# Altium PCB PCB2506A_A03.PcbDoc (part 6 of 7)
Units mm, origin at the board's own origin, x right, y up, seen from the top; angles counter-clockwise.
Board outline 115 x 60 mm, 6 copper layers (Top Layer, Signal Layer 2, Signal Layer 3, Signal Layer 4, Signal Layer 5, Bottom Layer), stack 1.555 mm thick; 376 components, 290 nets, 1297 pads, 901 vias.
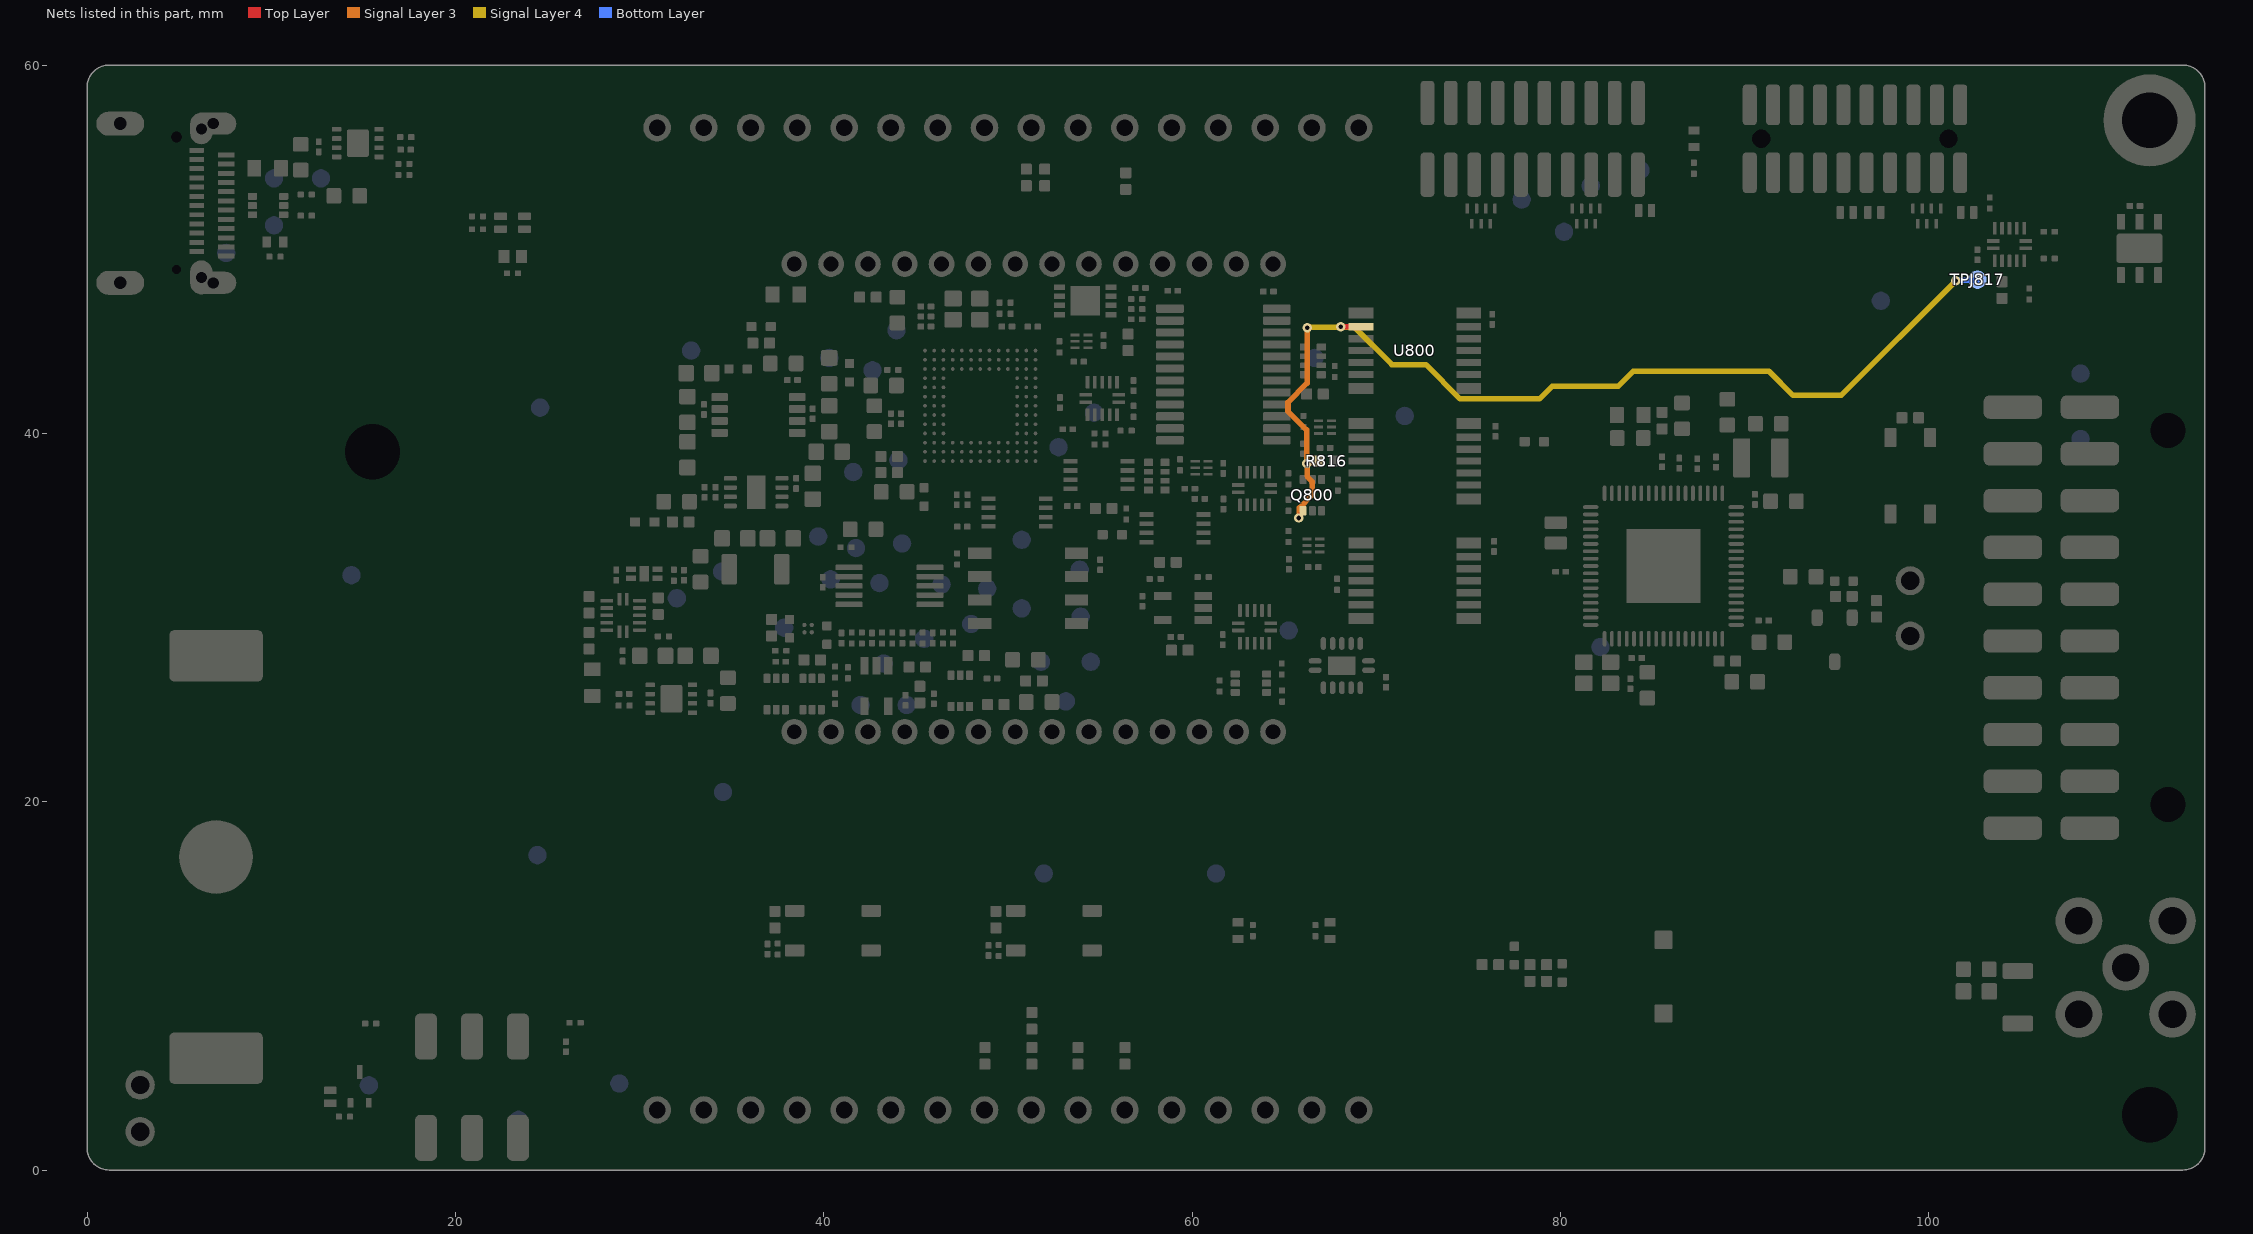
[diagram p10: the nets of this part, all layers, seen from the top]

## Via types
v1: diameter 0.508, hole 0.25, Top Layer to Bottom Layer, tented both sides, 901 vias

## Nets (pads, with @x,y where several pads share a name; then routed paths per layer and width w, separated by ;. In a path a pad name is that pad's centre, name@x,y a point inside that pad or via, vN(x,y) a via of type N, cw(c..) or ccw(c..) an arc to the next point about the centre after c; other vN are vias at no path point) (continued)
VTREF: Q800.4 R816.2 TPJ817.1 U800.2 | length 55.4
  Top Layer w0.3: v1(65.786,35.408) 65.826,35.447 65.826,35.53 66.033,35.738 Q800.4@66.033,35.8 ; v1(66.22,38.366) 66.26,38.406 66.807,38.406 R816.2@66.848,38.447 ; v1(68.083,45.801) 69.145,45.801 U800.2@69.148,45.798
  Signal Layer 3 w0.3: v1(65.786,35.408) 65.826,35.447 65.826,35.955 66.526,36.656 66.526,37.383 66.248,37.662 66.248,38.35 v1@66.218,38.379 ; v1(66.22,38.366) 66.218,38.368 66.218,40.192 65.211,41.199 65.211,41.691 66.252,42.731 v1(66.252,45.745)
  Signal Layer 4 w0.3: v1(66.252,45.745) 66.28,45.773 68.055,45.773 v1(68.083,45.801) ; v1@68.301,45.756 68.837,45.756 70.854,43.739 72.695,43.739 74.562,41.872 78.868,41.872 79.542,42.546 79.546,42.546 79.553,42.553 83.135,42.553 83.961,43.378 91.318,43.378 92.634,42.062 95.25,42.062 v1(101.473,48.285)
  Bottom Layer w0.3: v1(101.473,48.285) 101.505,48.318 102.618,48.318 TPJ817.1@102.65,48.35
pads on no net: D101.3 D800.5 D801.1 M2.1 M3.1 P101.M1 P101.M2 P601.25@1.8,56.82 P601.26@1.8,48.18 P601.27@6.2,56.525 P601.27@6.85,56.82 P601.28@6.2,48.475 P601.28@6.85,48.18 P601.A2 P601.A3 P601.A8 P601.A10 P601.A11 P601.B2 P601.B3 P601.B8 P601.B10 P601.B11 P601.M1 P601.M2 P800.7 P800.11 P800.13 P801.10 P801.12 P801.14 P801.16 P801.18 P801.20 P801.M1 P801.M2 RP800.2 RP800.7 U102.3 U102.4 U102.7 U600.8 U701.8 U808.8 U808.9 U808.10 U810.17 U900.B11 U900.E12 U900.F12 U900.G2 U900.H2 U900.J2 U900.L3 U900.L8 U900.L12 U900.M4 U900.M12 U900.N7 U900.N12 U901.9 U902.7

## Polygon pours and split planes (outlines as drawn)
VMCU on Signal Layer 5 "VMCU_L5" (solid, remove dead copper, pour order 5): 29.261,6.425 33.223,10.387 33.223,21.184 37.821,25.781 73.106,25.781 74.524,27.153 74.524,39.954 75.286,40.716 85.928,40.716 86.97,41.758 90.627,41.758 92.532,39.853 102.286,39.853 103.149,40.716 103.149,50.312 102.286,51.134 102.286,59.207 103.073,59.995 115,59.995 115,0 21.463,0 20.375,1.037 20.375,1.194 20.375,5.817 20.371,5.841 20.955,6.425
3V3 on Signal Layer 5 "3V3_L05_P014" (solid, remove dead copper, pour order 14): 18.587,44.526 27.259,44.526 29.439,42.291 41.595,42.291 43.798,40.056 45.314,40.056 46.673,38.697 46.673,35.878 44.975,34.18 39.463,34.18 38.049,32.766 38.049,30.226 36.601,28.778 33.223,28.778 28.804,24.359 25.908,24.359 16.84,33.426 14.732,33.426 14.199,32.893 14.199,30.099 17.875,26.423 17.875,8.425 19.391,6.909 29.009,6.909 32.614,10.514 32.614,21.464 37.515,26.365 73.076,26.365 73.939,27.229 73.939,39.954 75.235,41.25 85.649,41.25 86.69,42.291 90.653,42.291 92.569,40.375 102.249,40.375 102.692,40.818 102.692,50.114 102.006,50.8 102.006,59.284 101.815,59.475 99.825,59.475 99.4,59.05 99.4,53.782 95.993,50.375 77.682,50.375 70.656,57.299 68.451,57.301 63.372,52.222 21.32,52.222 19.238,54.305 13.513,54.305 12.802,53.594 12.802,50.388
5V on Signal Layer 5 "5V_L05_P013" (solid, remove dead copper, pour order 13): 29.108,41.783 26.822,44.069 18.491,44.069 18.161,44.348 12.319,50.19 12.319,53.975 13.208,54.864 19.877,54.864 21.782,52.925 63.212,52.925 67.945,57.658 71.018,57.658 77.851,50.825 95.85,50.825 99.035,54.01 99.035,58.979 98.563,59.45 7.913,59.45 7.65,59.187 7.65,36.927 8.377,36.2 12.903,36.2 14.554,34.595 16.637,34.595 26.264,24.968 28.6,24.968 32.791,29.159 36.398,29.159 37.541,30.302 37.541,32.766 39.446,34.671 44.577,34.671 46.228,36.322 46.228,38.1 44.768,39.56 43.624,39.56 41.402,41.783
GND on Signal Layer 5 "VCC Layer 5-GND" (solid, remove dead copper, pour order 15): 7.1,59.425 7.025,59.5 0.95,59.5 0.5,59.05 0.5,0.5 19.25,0.5 19.5,0.75 19.5,5.775 17.1,8.175 17.1,26.175 12.637,30.638 12.637,34.938 11.95,35.625 7.625,35.65 7.1,36.175
GND on Signal Layer 2 "GND_L2" (solid, remove dead copper, pour order 9): 0,0 0,60 125,60 125,0
GND on Top Layer "GND_L1" (solid, remove dead copper, pour order 2): 0,0 0,60 125,60 125,0
GND on Bottom Layer "GND_L6" (solid, remove dead copper, pour order 8): 0,0 0,60 125,60 125,0
GND on Signal Layer 3 "GND_L3" (solid, remove dead copper, pour order 11): 0,0 0,60 125,60 125,0
GND on Signal Layer 4 "GND_L4" (solid, remove dead copper, pour order 12): 0.008,-0.345 0.008,59.655 125.008,59.655 125.008,-0.345

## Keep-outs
Bottom Layer:
  region: 68.251,54.062 ccw(c69.051,54.062) 69.051,53.262 ccw(c69.051,54.062) 69.851,54.062 ccw(c69.051,54.062) 69.051,54.862 ccw(c69.051,54.062)
  region: 65.711,54.062 ccw(c66.511,54.062) 66.511,53.262 ccw(c66.511,54.062) 67.311,54.062 ccw(c66.511,54.062) 66.511,54.862 ccw(c66.511,54.062)
  region: 63.171,54.062 ccw(c63.971,54.062) 63.971,53.262 ccw(c63.971,54.062) 64.771,54.062 ccw(c63.971,54.062) 63.971,54.862 ccw(c63.971,54.062)
  region: 60.631,54.062 ccw(c61.431,54.062) 61.431,53.262 ccw(c61.431,54.062) 62.231,54.062 ccw(c61.431,54.062) 61.431,54.862 ccw(c61.431,54.062)
  region: 58.091,54.062 ccw(c58.891,54.062) 58.891,53.262 ccw(c58.891,54.062) 59.691,54.062 ccw(c58.891,54.062) 58.891,54.862 ccw(c58.891,54.062)
  region: 55.551,54.062 ccw(c56.351,54.062) 56.351,53.262 ccw(c56.351,54.062) 57.151,54.062 ccw(c56.351,54.062) 56.351,54.862 ccw(c56.351,54.062)
  region: 53.011,54.062 ccw(c53.811,54.062) 53.811,53.262 ccw(c53.811,54.062) 54.611,54.062 ccw(c53.811,54.062) 53.811,54.862 ccw(c53.811,54.062)
  region: 50.471,54.062 ccw(c51.271,54.062) 51.271,53.262 ccw(c51.271,54.062) 52.071,54.062 ccw(c51.271,54.062) 51.271,54.862 ccw(c51.271,54.062)
  region: 47.931,54.062 ccw(c48.731,54.062) 48.731,53.262 ccw(c48.731,54.062) 49.531,54.062 ccw(c48.731,54.062) 48.731,54.862 ccw(c48.731,54.062)
  region: 45.391,54.062 ccw(c46.191,54.062) 46.191,53.262 ccw(c46.191,54.062) 46.991,54.062 ccw(c46.191,54.062) 46.191,54.862 ccw(c46.191,54.062)
  region: 42.851,54.062 ccw(c43.651,54.062) 43.651,53.262 ccw(c43.651,54.062) 44.451,54.062 ccw(c43.651,54.062) 43.651,54.862 ccw(c43.651,54.062)
  region: 40.311,54.062 ccw(c41.111,54.062) 41.111,53.262 ccw(c41.111,54.062) 41.911,54.062 ccw(c41.111,54.062) 41.111,54.862 ccw(c41.111,54.062)
  region: 37.771,54.062 ccw(c38.571,54.062) 38.571,53.262 ccw(c38.571,54.062) 39.371,54.062 ccw(c38.571,54.062) 38.571,54.862 ccw(c38.571,54.062)
  region: 35.231,54.062 ccw(c36.031,54.062) 36.031,53.262 ccw(c36.031,54.062) 36.831,54.062 ccw(c36.031,54.062) 36.031,54.862 ccw(c36.031,54.062)
  region: 32.691,54.062 ccw(c33.491,54.062) 33.491,53.262 ccw(c33.491,54.062) 34.291,54.062 ccw(c33.491,54.062) 33.491,54.862 ccw(c33.491,54.062)
  region: 30.151,54.062 ccw(c30.951,54.062) 30.951,53.262 ccw(c30.951,54.062) 31.751,54.062 ccw(c30.951,54.062) 30.951,54.862 ccw(c30.951,54.062)
  region: 30.151,54.062 ccw(c30.951,54.062) 30.951,53.262 ccw(c30.951,54.062) 31.751,54.062 ccw(c30.951,54.062) 30.951,54.862 ccw(c30.951,54.062)
  region: 30.151,56.602 ccw(c30.951,56.602) 30.951,55.802 ccw(c30.951,56.602) 31.751,56.602 ccw(c30.951,56.602) 30.951,57.402 ccw(c30.951,56.602)
  region: 68.251,56.602 ccw(c69.051,56.602) 69.051,55.802 ccw(c69.051,56.602) 69.851,56.602 ccw(c69.051,56.602) 69.051,57.402 ccw(c69.051,56.602)
  region: 65.711,56.602 ccw(c66.511,56.602) 66.511,55.802 ccw(c66.511,56.602) 67.311,56.602 ccw(c66.511,56.602) 66.511,57.402 ccw(c66.511,56.602)
  region: 63.171,56.602 ccw(c63.971,56.602) 63.971,55.802 ccw(c63.971,56.602) 64.771,56.602 ccw(c63.971,56.602) 63.971,57.402 ccw(c63.971,56.602)
  region: 60.631,56.602 ccw(c61.431,56.602) 61.431,55.802 ccw(c61.431,56.602) 62.231,56.602 ccw(c61.431,56.602) 61.431,57.402 ccw(c61.431,56.602)
  region: 58.091,56.602 ccw(c58.891,56.602) 58.891,55.802 ccw(c58.891,56.602) 59.691,56.602 ccw(c58.891,56.602) 58.891,57.402 ccw(c58.891,56.602)
  region: 55.551,56.602 ccw(c56.351,56.602) 56.351,55.802 ccw(c56.351,56.602) 57.151,56.602 ccw(c56.351,56.602) 56.351,57.402 ccw(c56.351,56.602)
  region: 53.011,56.602 ccw(c53.811,56.602) 53.811,55.802 ccw(c53.811,56.602) 54.611,56.602 ccw(c53.811,56.602) 53.811,57.402 ccw(c53.811,56.602)
  region: 50.471,56.602 ccw(c51.271,56.602) 51.271,55.802 ccw(c51.271,56.602) 52.071,56.602 ccw(c51.271,56.602) 51.271,57.402 ccw(c51.271,56.602)
  region: 47.931,56.602 ccw(c48.731,56.602) 48.731,55.802 ccw(c48.731,56.602) 49.531,56.602 ccw(c48.731,56.602) 48.731,57.402 ccw(c48.731,56.602)
  region: 45.391,56.602 ccw(c46.191,56.602) 46.191,55.802 ccw(c46.191,56.602) 46.991,56.602 ccw(c46.191,56.602) 46.191,57.402 ccw(c46.191,56.602)
  region: 42.851,56.602 ccw(c43.651,56.602) 43.651,55.802 ccw(c43.651,56.602) 44.451,56.602 ccw(c43.651,56.602) 43.651,57.402 ccw(c43.651,56.602)
  region: 40.311,56.602 ccw(c41.111,56.602) 41.111,55.802 ccw(c41.111,56.602) 41.911,56.602 ccw(c41.111,56.602) 41.111,57.402 ccw(c41.111,56.602)
  region: 37.771,56.602 ccw(c38.571,56.602) 38.571,55.802 ccw(c38.571,56.602) 39.371,56.602 ccw(c38.571,56.602) 38.571,57.402 ccw(c38.571,56.602)
  region: 35.231,56.602 ccw(c36.031,56.602) 36.031,55.802 ccw(c36.031,56.602) 36.831,56.602 ccw(c36.031,56.602) 36.031,57.402 ccw(c36.031,56.602)
  region: 32.691,56.602 ccw(c33.491,56.602) 33.491,55.802 ccw(c33.491,56.602) 34.291,56.602 ccw(c33.491,56.602) 33.491,57.402 ccw(c33.491,56.602)
  region: 68.251,3.262 ccw(c69.051,3.262) 69.051,2.462 ccw(c69.051,3.262) 69.851,3.262 ccw(c69.051,3.262) 69.051,4.062 ccw(c69.051,3.262)
  region: 65.711,3.262 ccw(c66.511,3.262) 66.511,2.462 ccw(c66.511,3.262) 67.311,3.262 ccw(c66.511,3.262) 66.511,4.062 ccw(c66.511,3.262)
  region: 63.171,3.262 ccw(c63.971,3.262) 63.971,2.462 ccw(c63.971,3.262) 64.771,3.262 ccw(c63.971,3.262) 63.971,4.062 ccw(c63.971,3.262)
  region: 60.631,3.262 ccw(c61.431,3.262) 61.431,2.462 ccw(c61.431,3.262) 62.231,3.262 ccw(c61.431,3.262) 61.431,4.062 ccw(c61.431,3.262)
  region: 58.091,3.262 ccw(c58.891,3.262) 58.891,2.462 ccw(c58.891,3.262) 59.691,3.262 ccw(c58.891,3.262) 58.891,4.062 ccw(c58.891,3.262)
  region: 55.551,3.262 ccw(c56.351,3.262) 56.351,2.462 ccw(c56.351,3.262) 57.151,3.262 ccw(c56.351,3.262) 56.351,4.062 ccw(c56.351,3.262)
  region: 53.011,3.262 ccw(c53.811,3.262) 53.811,2.462 ccw(c53.811,3.262) 54.611,3.262 ccw(c53.811,3.262) 53.811,4.062 ccw(c53.811,3.262)
  region: 50.471,3.262 ccw(c51.271,3.262) 51.271,2.462 ccw(c51.271,3.262) 52.071,3.262 ccw(c51.271,3.262) 51.271,4.062 ccw(c51.271,3.262)
  region: 47.931,3.262 ccw(c48.731,3.262) 48.731,2.462 ccw(c48.731,3.262) 49.531,3.262 ccw(c48.731,3.262) 48.731,4.062 ccw(c48.731,3.262)
  region: 45.391,3.262 ccw(c46.191,3.262) 46.191,2.462 ccw(c46.191,3.262) 46.991,3.262 ccw(c46.191,3.262) 46.191,4.062 ccw(c46.191,3.262)
  region: 42.851,3.262 ccw(c43.651,3.262) 43.651,2.462 ccw(c43.651,3.262) 44.451,3.262 ccw(c43.651,3.262) 43.651,4.062 ccw(c43.651,3.262)
  region: 40.311,3.262 ccw(c41.111,3.262) 41.111,2.462 ccw(c41.111,3.262) 41.911,3.262 ccw(c41.111,3.262) 41.111,4.062 ccw(c41.111,3.262)
  region: 37.771,3.262 ccw(c38.571,3.262) 38.571,2.462 ccw(c38.571,3.262) 39.371,3.262 ccw(c38.571,3.262) 38.571,4.062 ccw(c38.571,3.262)
  region: 35.231,3.262 ccw(c36.031,3.262) 36.031,2.462 ccw(c36.031,3.262) 36.831,3.262 ccw(c36.031,3.262) 36.031,4.062 ccw(c36.031,3.262)
  region: 32.691,3.262 ccw(c33.491,3.262) 33.491,2.462 ccw(c33.491,3.262) 34.291,3.262 ccw(c33.491,3.262) 33.491,4.062 ccw(c33.491,3.262)
  region: 30.151,3.262 ccw(c30.951,3.262) 30.951,2.462 ccw(c30.951,3.262) 31.751,3.262 ccw(c30.951,3.262) 30.951,4.062 ccw(c30.951,3.262)
  region: 30.151,3.262 ccw(c30.951,3.262) 30.951,2.462 ccw(c30.951,3.262) 31.751,3.262 ccw(c30.951,3.262) 30.951,4.062 ccw(c30.951,3.262)
  region: 30.151,5.802 ccw(c30.951,5.802) 30.951,5.002 ccw(c30.951,5.802) 31.751,5.802 ccw(c30.951,5.802) 30.951,6.602 ccw(c30.951,5.802)
  region: 68.251,5.802 ccw(c69.051,5.802) 69.051,5.002 ccw(c69.051,5.802) 69.851,5.802 ccw(c69.051,5.802) 69.051,6.602 ccw(c69.051,5.802)
  region: 65.711,5.802 ccw(c66.511,5.802) 66.511,5.002 ccw(c66.511,5.802) 67.311,5.802 ccw(c66.511,5.802) 66.511,6.602 ccw(c66.511,5.802)
  region: 63.171,5.802 ccw(c63.971,5.802) 63.971,5.002 ccw(c63.971,5.802) 64.771,5.802 ccw(c63.971,5.802) 63.971,6.602 ccw(c63.971,5.802)
  region: 60.631,5.802 ccw(c61.431,5.802) 61.431,5.002 ccw(c61.431,5.802) 62.231,5.802 ccw(c61.431,5.802) 61.431,6.602 ccw(c61.431,5.802)
  region: 58.091,5.802 ccw(c58.891,5.802) 58.891,5.002 ccw(c58.891,5.802) 59.691,5.802 ccw(c58.891,5.802) 58.891,6.602 ccw(c58.891,5.802)
  region: 55.551,5.802 ccw(c56.351,5.802) 56.351,5.002 ccw(c56.351,5.802) 57.151,5.802 ccw(c56.351,5.802) 56.351,6.602 ccw(c56.351,5.802)
  region: 53.011,5.802 ccw(c53.811,5.802) 53.811,5.002 ccw(c53.811,5.802) 54.611,5.802 ccw(c53.811,5.802) 53.811,6.602 ccw(c53.811,5.802)
  region: 50.471,5.802 ccw(c51.271,5.802) 51.271,5.002 ccw(c51.271,5.802) 52.071,5.802 ccw(c51.271,5.802) 51.271,6.602 ccw(c51.271,5.802)
  region: 47.931,5.802 ccw(c48.731,5.802) 48.731,5.002 ccw(c48.731,5.802) 49.531,5.802 ccw(c48.731,5.802) 48.731,6.602 ccw(c48.731,5.802)
  region: 45.391,5.802 ccw(c46.191,5.802) 46.191,5.002 ccw(c46.191,5.802) 46.991,5.802 ccw(c46.191,5.802) 46.191,6.602 ccw(c46.191,5.802)
  region: 42.851,5.802 ccw(c43.651,5.802) 43.651,5.002 ccw(c43.651,5.802) 44.451,5.802 ccw(c43.651,5.802) 43.651,6.602 ccw(c43.651,5.802)
  region: 40.311,5.802 ccw(c41.111,5.802) 41.111,5.002 ccw(c41.111,5.802) 41.911,5.802 ccw(c41.111,5.802) 41.111,6.602 ccw(c41.111,5.802)
  region: 37.771,5.802 ccw(c38.571,5.802) 38.571,5.002 ccw(c38.571,5.802) 39.371,5.802 ccw(c38.571,5.802) 38.571,6.602 ccw(c38.571,5.802)
  region: 35.231,5.802 ccw(c36.031,5.802) 36.031,5.002 ccw(c36.031,5.802) 36.831,5.802 ccw(c36.031,5.802) 36.031,6.602 ccw(c36.031,5.802)
  region: 32.691,5.802 ccw(c33.491,5.802) 33.491,5.002 ccw(c33.491,5.802) 34.291,5.802 ccw(c33.491,5.802) 33.491,6.602 ccw(c33.491,5.802)
  region: 103.5,19 cw(c103.5,18.5) 104,18.5 cw(c103.5,18.5) 103.5,18 cw(c103.5,18.5) 103,18.5 cw(c103.5,18.5)
  region: 108.25,40.2 cw(c108.25,39.699) 108.75,39.7 cw(c108.25,39.7) 108.25,39.2 cw(c108.25,39.7) 107.75,39.7 cw(c108.25,39.699)
  region: 108.25,43.748 cw(c108.25,43.248) 108.75,43.248 cw(c108.25,43.248) 108.25,42.748 cw(c108.25,43.248) 107.75,43.248 cw(c108.25,43.248)
  region: 107,54.2 cw(c107,53.7) 107.5,53.7 cw(c107,53.7) 107,53.2 cw(c107,53.7) 106.5,53.7 cw(c107,53.7)
  region: 105.4,52.498 cw(c105.4,51.998) 105.9,51.998 cw(c105.4,51.998) 105.4,51.498 cw(c105.4,51.998) 104.9,51.998 cw(c105.4,51.998)
  region: 104.45,54.2 cw(c104.45,53.7) 104.95,53.7 cw(c104.45,53.7) 104.45,53.2 cw(c104.45,53.7) 103.95,53.7 cw(c104.45,53.7)
  region: 103.399,52.498 cw(c103.399,51.998) 103.899,51.998 cw(c103.399,51.998) 103.399,51.498 cw(c103.399,51.998) 102.899,51.998 cw(c103.399,51.998)
  region: 102.649,48.848 cw(c102.649,48.348) 103.149,48.348 cw(c102.649,48.348) 102.649,47.848 cw(c102.649,48.348) 102.149,48.348 cw(c102.649,48.348)
  region: 97.399,47.7 cw(c97.399,47.2) 97.899,47.2 cw(c97.399,47.2) 97.399,46.7 cw(c97.399,47.2) 96.899,47.2 cw(c97.399,47.2)
  region: 92.525,52.432 cw(c92.525,51.932) 93.025,51.932 cw(c92.525,51.932) 92.525,51.432 cw(c92.525,51.932) 92.025,51.932 cw(c92.525,51.932)
  region: 93.541,54.21 cw(c93.541,53.71) 94.041,53.71 cw(c93.541,53.71) 93.541,53.21 cw(c93.541,53.71) 93.041,53.71 cw(c93.541,53.71)
  region: 90.493,52.432 cw(c90.493,51.932) 90.993,51.932 cw(c90.493,51.932) 90.493,51.432 cw(c90.493,51.932) 89.993,51.932 cw(c90.493,51.932)
  region: 88.461,52.432 cw(c88.461,51.932) 88.961,51.932 cw(c88.461,51.932) 88.461,51.432 cw(c88.461,51.932) 87.961,51.932 cw(c88.461,51.932)
  region: 89.477,54.21 cw(c89.477,53.71) 89.977,53.71 cw(c89.477,53.71) 89.477,53.21 cw(c89.477,53.71) 88.977,53.71 cw(c89.477,53.71)
  region: 87.466,54.206 cw(c87.467,53.706) 87.967,53.706 cw(c87.466,53.707) 87.466,53.206 cw(c87.466,53.706) 86.967,53.706 cw(c87.467,53.706)
  region: 84.349,54.799 cw(c84.349,54.299) 84.849,54.3 cw(c84.349,54.3) 84.349,53.799 cw(c84.349,54.299) 83.849,54.299 cw(c84.349,54.299)
  region: 85.4,52.198 cw(c85.4,51.698) 85.9,51.699 cw(c85.4,51.699) 85.4,51.199 cw(c85.4,51.698) 84.9,51.698 cw(c85.4,51.698)
  region: 93.449,42.798 cw(c93.45,42.298) 93.95,42.298 cw(c93.449,42.298) 93.449,41.798 cw(c93.449,42.298) 92.949,42.298 cw(c93.45,42.298)
  region: 86.15,40.05 cw(c86.15,39.55) 86.65,39.55 cw(c86.149,39.55) 86.149,39.05 cw(c86.149,39.55) 85.65,39.55 cw(c86.15,39.55)
  region: 81.649,53.949 cw(c81.649,53.449) 82.149,53.449 cw(c81.649,53.449) 81.649,52.949 cw(c81.649,53.449) 81.149,53.449 cw(c81.649,53.448)
  region: 77.9,53.199 cw(c77.9,52.699) 78.4,52.699 cw(c77.9,52.699) 77.9,52.199 cw(c77.9,52.699) 77.4,52.699 cw(c77.9,52.699)
  region: 80.201,51.449 cw(c80.201,50.949) 80.701,50.949 cw(c80.201,50.949) 80.201,50.449 cw(c80.201,50.949) 79.701,50.949 cw(c80.201,50.949)
  region: 77.399,48.498 cw(c77.399,47.998) 77.899,47.998 cw(c77.399,47.998) 77.399,47.498 cw(c77.399,47.998) 76.899,47.998 cw(c77.399,47.998)
  region: 75.4,48.498 cw(c75.4,47.998) 75.9,47.998 cw(c75.4,47.998) 75.4,47.498 cw(c75.4,47.998) 74.9,47.998 cw(c75.4,47.998)
  region: 73.399,48.498 cw(c73.399,47.998) 73.899,47.998 cw(c73.399,47.998) 73.399,47.498 cw(c73.399,47.998) 72.899,47.998 cw(c73.399,47.998)
  region: 77.399,46.298 cw(c77.399,45.798) 77.899,45.798 cw(c77.399,45.798) 77.399,45.298 cw(c77.399,45.798) 76.899,45.798 cw(c77.399,45.798)
  region: 75.4,46.298 cw(c75.4,45.798) 75.9,45.798 cw(c75.4,45.798) 75.4,45.298 cw(c75.4,45.798) 74.9,45.798 cw(c75.4,45.798)
  region: 73.399,46.298 cw(c73.399,45.798) 73.899,45.798 cw(c73.399,45.798) 73.399,45.298 cw(c73.399,45.798) 72.899,45.798 cw(c73.399,45.798)
  region: 71.4,46.298 cw(c71.4,45.798) 71.9,45.798 cw(c71.4,45.798) 71.4,45.298 cw(c71.4,45.798) 70.9,45.798 cw(c71.4,45.798)
  region: 73.399,43.598 cw(c73.399,43.098) 73.899,43.098 cw(c73.399,43.098) 73.399,42.598 cw(c73.399,43.098) 72.899,43.098 cw(c73.399,43.098)
  region: 71.55,41.449 cw(c71.55,40.949) 72.05,40.949 cw(c71.55,40.949) 71.55,40.449 cw(c71.55,40.949) 71.05,40.949 cw(c71.55,40.949)
  region: 66.65,44.599 cw(c66.65,44.099) 67.15,44.099 cw(c66.65,44.099) 66.65,43.599 cw(c66.65,44.099) 66.15,44.099 cw(c66.65,44.099)
  region: 94.199,12.348 cw(c94.199,11.848) 94.699,11.848 cw(c94.199,11.849) 94.199,11.348 cw(c94.199,11.848) 93.699,11.848 cw(c94.199,11.848)
  region: 96.8,11.8 cw(c96.8,11.3) 97.3,11.3 cw(c96.8,11.3) 96.8,10.8 cw(c96.8,11.3) 96.3,11.3 cw(c96.8,11.3)
  region: 93.249,9.948 cw(c93.249,9.448) 93.749,9.448 cw(c93.249,9.448) 93.249,8.948 cw(c93.249,9.448) 92.749,9.448 cw(c93.249,9.448)
  region: 96.5,9.148 cw(c96.5,8.648) 97,8.648 cw(c96.5,8.648) 96.5,8.148 cw(c96.5,8.648) 96,8.648 cw(c96.5,8.648)
  region: 95.7,6.55 cw(c95.7,6.05) 96.2,6.05 cw(c95.7,6.05) 95.7,5.55 cw(c95.7,6.05) 95.2,6.05 cw(c95.7,6.049)
  region: 93.249,7.398 cw(c93.249,6.898) 93.749,6.898 cw(c93.249,6.898) 93.249,6.398 cw(c93.249,6.898) 92.749,6.898 cw(c93.249,6.898)
  region: 81.499,10.949 cw(c81.499,10.449) 81.999,10.449 cw(c81.499,10.449) 81.499,9.949 cw(c81.499,10.449) 80.999,10.449 cw(c81.499,10.449)
  region: 77.249,10.949 cw(c77.249,10.449) 77.749,10.449 cw(c77.249,10.449) 77.249,9.949 cw(c77.249,10.449) 76.749,10.449 cw(c77.249,10.449)
  region: 72.949,10.949 cw(c72.949,10.449) 73.449,10.449 cw(c72.949,10.449) 72.949,9.949 cw(c72.949,10.449) 72.449,10.449 cw(c72.949,10.449)
  region: 74.1,6.748 cw(c74.1,6.248) 74.6,6.248 cw(c74.1,6.248) 74.1,5.748 cw(c74.1,6.248) 73.6,6.248 cw(c74.1,6.248)
  region: 54.674,41.624 cw(c54.674,41.124) 55.174,41.125 cw(c54.674,41.125) 54.674,40.625 cw(c54.674,41.124) 54.174,41.124 cw(c54.674,41.124)
  region: 52.749,39.75 cw(c52.749,39.25) 53.249,39.25 cw(c52.748,39.25) 52.748,38.75 cw(c52.748,39.25) 52.249,39.25 cw(c52.749,39.25)
  region: 50.75,34.723 cw(c50.75,34.223) 51.25,34.223 cw(c50.749,34.223) 50.75,33.723 cw(c50.75,34.223) 50.25,34.223 cw(c50.75,34.223)
  region: 53.899,33.098 cw(c53.899,32.598) 54.399,32.598 cw(c53.899,32.598) 53.899,32.098 cw(c53.899,32.598) 53.399,32.598 cw(c53.899,32.598)
  region: 50.75,31 cw(c50.75,30.5) 51.25,30.5 cw(c50.749,30.5) 50.75,30 cw(c50.75,30.5) 50.25,30.5 cw(c50.75,30.5)
  region: 53.95,30.55 cw(c53.95,30.05) 54.45,30.05 cw(c53.95,30.05) 53.95,29.55 cw(c53.95,30.05) 53.45,30.05 cw(c53.95,30.05)
  region: 54.499,28.099 cw(c54.499,27.599) 54.999,27.599 cw(c54.498,27.599) 54.499,27.099 cw(c54.499,27.599) 53.999,27.599 cw(c54.499,27.599)
  region: 51.799,28.099 cw(c51.799,27.599) 52.299,27.599 cw(c51.798,27.599) 51.799,27.099 cw(c51.799,27.599) 51.299,27.599 cw(c51.799,27.599)
  region: 53.15,25.95 cw(c53.15,25.45) 53.65,25.45 cw(c53.15,25.45) 53.15,24.95 cw(c53.15,25.45) 52.65,25.45 cw(c53.15,25.45)
  region: 47.999,30.149 cw(c47.999,29.649) 48.499,29.649 cw(c47.999,29.649) 47.999,29.149 cw(c47.999,29.649) 47.499,29.649 cw(c47.999,29.649)
  region: 45.449,29.349 cw(c45.449,28.849) 45.949,28.849 cw(c45.448,28.849) 45.449,28.349 cw(c45.449,28.849) 44.949,28.849 cw(c45.449,28.849)
  region: 47,25.749 cw(c47.001,25.249) 47.501,25.25 cw(c47,25.25) 47,24.75 cw(c47,25.249) 46.501,25.249 cw(c47.001,25.249)
  region: 43.249,28 cw(c43.249,27.5) 43.749,27.5 cw(c43.249,27.5) 43.249,27 cw(c43.249,27.5) 42.749,27.5 cw(c43.249,27.5)
  region: 44.499,25.749 cw(c44.499,25.249) 44.999,25.25 cw(c44.499,25.25) 44.499,24.75 cw(c44.499,25.249) 43.999,25.249 cw(c44.499,25.249)
  region: 41.999,25.749 cw(c41.999,25.249) 42.499,25.25 cw(c41.999,25.25) 41.999,24.75 cw(c41.999,25.249) 41.499,25.249 cw(c41.999,25.249)
  region: 61.301,16.598 cw(c61.301,16.098) 61.801,16.098 cw(c61.301,16.098) 61.301,15.598 cw(c61.301,16.098) 60.801,16.098 cw(c61.301,16.098)
  region: 51.951,16.598 cw(c51.951,16.098) 52.451,16.098 cw(c51.951,16.098) 51.951,15.598 cw(c51.951,16.098) 51.451,16.098 cw(c51.951,16.098)
  region: 34.524,21.025 cw(c34.524,20.525) 35.024,20.525 cw(c34.524,20.525) 34.524,20.025 cw(c34.524,20.525) 34.024,20.525 cw(c34.524,20.525)
  region: 24.45,17.599 cw(c24.45,17.099) 24.95,17.099 cw(c24.45,17.099) 24.45,16.599 cw(c24.45,17.099) 23.95,17.099 cw(c24.45,17.098)
  region: 15.649,26.448 cw(c15.649,25.948) 16.149,25.948 cw(c15.649,25.948) 15.649,25.448 cw(c15.649,25.948) 15.149,25.948 cw(c15.649,25.948)
  region: 12.05,26.448 cw(c12.05,25.948) 12.55,25.948 cw(c12.05,25.948) 12.05,25.448 cw(c12.05,25.948) 11.55,25.948 cw(c12.05,25.948)
  region: 12.025,29.773 cw(c12.025,29.273) 12.525,29.273 cw(c12.025,29.273) 12.025,28.773 cw(c12.025,29.273) 11.525,29.273 cw(c12.025,29.273)
  region: 9.475,29.798 cw(c9.475,29.298) 9.975,29.298 cw(c9.474,29.298) 9.475,28.798 cw(c9.475,29.298) 8.975,29.298 cw(c9.475,29.298)
  region: 14.349,32.798 cw(c14.349,32.298) 14.849,32.298 cw(c14.349,32.298) 14.349,31.798 cw(c14.349,32.298) 13.849,32.298 cw(c14.349,32.298)
  region: 10.399,32.249 cw(c10.399,31.749) 10.899,31.749 cw(c10.399,31.75) 10.399,31.249 cw(c10.399,31.749) 9.899,31.749 cw(c10.399,31.749)
  region: 10.399,34.899 cw(c10.399,34.399) 10.899,34.399 cw(c10.399,34.399) 10.399,33.899 cw(c10.399,34.399) 9.899,34.399 cw(c10.399,34.398)
  region: 18.446,49.044 cw(c18.446,48.544) 18.946,48.544 cw(c18.446,48.544) 18.446,48.044 cw(c18.446,48.544) 17.946,48.544 cw(c18.446,48.544)
  region: 15.906,50.314 cw(c15.906,49.814) 16.406,49.814 cw(c15.906,49.814) 15.906,49.314 cw(c15.906,49.814) 15.406,49.814 cw(c15.906,49.814)
  region: 18.446,51.584 cw(c18.446,51.084) 18.946,51.084 cw(c18.446,51.084) 18.446,50.584 cw(c18.446,51.084) 17.946,51.084 cw(c18.446,51.084)
  region: 15.906,52.854 cw(c15.906,52.354) 16.406,52.354 cw(c15.906,52.354) 15.906,51.854 cw(c15.906,52.354) 15.406,52.354 cw(c15.906,52.354)
  region: 18.446,54.124 cw(c18.446,53.624) 18.946,53.624 cw(c18.446,53.624) 18.446,53.124 cw(c18.446,53.624) 17.946,53.624 cw(c18.446,53.624)
  region: 15.906,55.394 cw(c15.906,54.894) 16.406,54.894 cw(c15.906,54.894) 15.906,54.394 cw(c15.906,54.894) 15.406,54.894 cw(c15.906,54.894)
  region: 12.7,54.35 cw(c12.7,53.85) 13.2,53.85 cw(c12.7,53.85) 12.7,53.35 cw(c12.7,53.85) 12.2,53.85 cw(c12.7,53.85)
  region: 10.15,54.35 cw(c10.15,53.85) 10.65,53.85 cw(c10.15,53.85) 10.15,53.35 cw(c10.15,53.85) 9.65,53.85 cw(c10.15,53.85)
  region: 10.15,51.8 cw(c10.15,51.3) 10.65,51.3 cw(c10.15,51.3) 10.15,50.8 cw(c10.15,51.3) 9.65,51.3 cw(c10.15,51.3)
  region: 7.549,50.299 cw(c7.549,49.799) 8.049,49.799 cw(c7.549,49.799) 7.549,49.299 cw(c7.549,49.799) 7.049,49.799 cw(c7.549,49.798)
  region: 24.6,41.899 cw(c24.6,41.399) 25.1,41.399 cw(c24.6,41.399) 24.6,40.899 cw(c24.6,41.399) 24.1,41.399 cw(c24.6,41.399)
  region: 36.249,37.548 cw(c36.249,37.048) 36.749,37.048 cw(c36.249,37.048) 36.249,36.548 cw(c36.249,37.048) 35.749,37.048 cw(c36.249,37.048)
  region: 38.999,37.548 cw(c39,37.048) 39.5,37.048 cw(c38.999,37.048) 38.999,36.548 cw(c38.999,37.048) 38.5,37.048 cw(c39,37.048)
  region: 41.6,38.399 cw(c41.6,37.899) 42.101,37.899 cw(c41.6,37.899) 41.6,37.399 cw(c41.6,37.899) 41.1,37.899 cw(c41.601,37.899)
  region: 44.049,39.049 cw(c44.049,38.549) 44.549,38.549 cw(c44.049,38.549) 44.049,38.049 cw(c44.049,38.549) 43.549,38.549 cw(c44.049,38.549)
  region: 42.649,43.923 cw(c42.65,43.423) 43.15,43.423 cw(c42.649,43.423) 42.649,42.923 cw(c42.649,43.423) 42.149,43.423 cw(c42.65,43.423)
  region: 43.95,46.1 cw(c43.95,45.6) 44.45,45.6 cw(c43.95,45.6) 43.95,45.1 cw(c43.95,45.6) 43.45,45.6 cw(c43.95,45.6)
  region: 18.446,46.504 cw(c18.446,46.004) 18.946,46.004 cw(c18.446,46.004) 18.446,45.504 cw(c18.446,46.004) 17.946,46.004 cw(c18.446,46.004)

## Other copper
Top Layer:
  region net AEM_VMCU: 22.642,4.608 22.642,2.998 22.845,2.794 24.039,2.794 24.242,2.998 24.242,4.649 23.963,4.928 22.962,4.928
  region net VMCU: 20.142,4.597 20.142,3.023 20.345,2.819 21.539,2.819 21.742,3.023 21.742,4.674 21.463,4.953 20.498,4.953
  region net VMCU: 99.746,16.713 99.771,16.739 102.641,16.739 103.073,17.17 103.073,19.126 102.718,19.482 99.695,19.482 99.466,19.253 99.466,17.018 99.746,16.739
  pour cut-out: 89.518,25.958 89.746,25.958 90.146,25.958 90.146,29.616 89.518,29.616
  pour cut-out: 77.378,51.857 77.378,52.085 77.378,52.485 75.829,52.485 75.829,51.857
  pour cut-out: 71.542,52.822 71.77,52.822 72.17,52.822 72.17,54.372 71.542,54.372
  pour cut-out: 69.414,33.979 69.643,33.979 70.043,33.979 70.043,35.528 69.414,35.528
  pour cut-out: 37.582,48.753 37.582,48.524 37.582,48.124 39.132,48.124 39.132,48.753
  pour cut-out: 52.695,49.921 52.695,49.692 52.695,49.293 54.245,49.293 54.245,49.921
  pour cut-out: 44.104,45.958 43.876,45.958 43.476,45.958 43.476,44.409 44.104,44.409
  pour cut-out: 57.813,6.746 57.813,6.975 57.813,7.374 56.263,7.374 56.263,6.746
  pour cut-out: 58.064,53.518 57.276,56.354 55.88,55.702 55.88,53.594
  pour cut-out: 50.178,6.331 50.178,6.56 50.178,6.96 48.628,6.96 48.628,6.331
  region net N17065843: 89.937,36.075 89.937,35.894 90.018,35.814 90.907,35.814 91.034,35.814 91.11,35.89 91.11,36.144 90.983,36.271 89.992,36.271 89.916,36.195 89.937,36.174
  pour cut-out: 80.531,41.134 80.531,40.727 80.531,40.328 82.081,40.328 82.081,41.134
  pour cut-out: 75.881,42.328 75.474,42.328 75.075,42.328 75.075,40.779 75.881,40.779
  pour cut-out: 92.693,32.385 92.921,32.385 93.321,32.385 93.321,35.23 92.693,35.23
  pour cut-out: 93.929,30.066 93.929,29.837 93.929,29.437 95.606,29.437 95.606,30.066
  pour cut-out: 90.805,31.158 90.805,30.929 90.805,30.53 94.463,30.53 94.463,31.158
  pour cut-out: 71.564,36.62 71.564,36.391 71.564,35.992 74.232,35.992 74.232,36.62
  pour cut-out: 79.527,28.219 79.948,31.919 80.014,32.498 78.364,30.043
  pour cut-out: 78.943,32.983 79.571,32.983 79.571,35.763 78.943,35.763
  pour cut-out: 75.666,36.543 75.666,36.314 75.666,35.914 79.324,35.914 79.324,36.543
  pour cut-out: 59.919,28.27 61.417,28.27 61.417,29.489 59.919,29.489
  pour cut-out: 64.37,35.676 64.599,35.676 64.998,35.676 64.998,37.225 64.37,37.225
  pour cut-out: 106.077,47.715 106.305,47.715 106.705,47.715 106.705,49.265 106.077,49.265
  pour cut-out: 91.313,39.218 90.907,39.218 90.507,39.218 90.507,37.668 91.313,37.668
  pour cut-out: 97.995,31.978 96.67,31.978 96.27,31.978 96.27,31.369 97.995,31.369
  pour cut-out: 81.356,28.473 80.728,28.473 80.728,27.94 81.356,27.94
  pour cut-out: 37.827,12.509 38.056,12.509 38.456,12.509 38.456,14.059 37.827,14.059
  pour cut-out: 50.07,12.23 50.299,12.23 50.698,12.23 50.698,13.779 50.07,13.779
  pour cut-out: 5.813,50.745 5.813,50.516 5.813,50.117 7.362,50.117 7.362,50.745
  pour cut-out: 9.978,51.972 9.749,51.972 9.35,51.972 9.35,50.423 9.978,50.423
  pour cut-out: 10.211,54.31 10.211,54.938 6.074,54.938 6.074,54.31
  pour cut-out: 82.245,36.068 82.321,35.992 82.321,29.489 88.875,29.489 88.976,29.591 88.976,36.17 82.296,36.17 82.245,36.22
  pour cut-out: 45.222,48.047 45.222,48.275 45.222,48.675 43.672,48.675 43.672,48.047
  pour cut-out: 46.133,49.232 46.133,49.46 46.133,49.86 44.583,49.86 44.583,49.232
  pour cut-out: 56.133,49.232 56.133,49.46 56.133,49.86 54.583,49.86 54.583,49.232
  pour cut-out: 40.005,43.739 40.005,43.967 40.005,44.367 38.456,44.367 38.456,43.739
  pour cut-out: 34.366,41.834 34.595,41.834 34.994,41.834 34.994,43.383 34.366,43.383
  pour cut-out: 38.43,33.706 38.43,33.477 38.43,33.078 40.437,33.078 40.437,33.706
  pour cut-out: 51.729,31.858 51.729,31.63 51.729,31.23 54.534,31.23 54.534,31.858
  pour cut-out: 56.276,35.948 56.276,35.719 56.276,35.32 57.825,35.32 57.825,35.948
  pour cut-out: 60.391,41.206 60.391,40.977 60.391,40.577 61.94,40.577 61.94,41.206
  pour cut-out: 70.968,40.615 70.739,40.615 70.339,40.615 70.339,39.065 70.968,39.065
  pour cut-out: 74.279,39.608 73.558,41.478 73.558,41.878 72.009,41.878 72.009,41.25
  pour cut-out: 83.04,41.557 83.04,41.328 83.04,40.928 84.59,40.928 84.59,41.557
  pour cut-out: 71.476,51.45 71.476,51.221 71.476,50.93 73.026,50.394 73.026,51.45
  pour cut-out: 93.233,58.924 93.233,59.153 93.233,59.552 89.687,59.552 89.687,58.924
  pour cut-out: 94.92,52.304 95.148,52.304 95.548,52.304 95.548,53.854 94.92,53.854
  pour cut-out: 107.119,36.887 107.348,36.887 107.747,36.887 107.747,38.436 107.119,38.436
  pour cut-out: 109.659,36.912 109.888,36.912 110.287,36.912 110.287,38.461 109.659,38.461
  pour cut-out: 109.684,39.3 109.913,39.3 110.313,39.3 110.313,40.849 109.684,40.849
  pour cut-out: 107.119,39.274 107.348,39.274 107.747,39.274 107.747,40.824 107.119,40.824
  pour cut-out: 105.613,39.421 105.842,39.421 106.241,39.421 106.241,40.97 105.613,40.97
  pour cut-out: 89.027,29.287 89.027,28.038 92.055,28.038 92.055,29.287
  pour cut-out: 79.807,35.331 79.578,35.331 79.179,35.331 79.179,33.782 79.807,33.782
  pour cut-out: 71.003,30.499 71.003,30.727 71.003,31.127 69.454,31.127 69.454,30.499
  pour cut-out: 65.913,25.578 66.313,25.578 66.313,26.264 65.392,26.098
  pour cut-out: 50.622,23.774 50.622,23.546 50.622,23.146 52.172,23.146 52.172,23.774
  pour cut-out: 48.616,23.87 48.616,23.641 48.616,23.242 50.166,23.242 50.166,23.87
  pour cut-out: 42.57,23.87 42.57,23.242 48.057,23.242 48.057,23.87
  pour cut-out: 38.76,23.8 38.76,23.571 38.76,23.172 40.31,23.172 40.31,23.8
  pour cut-out: 81,15 90,15 90,6 81,6
  region net N16809528: 10.542,26.275 10.542,29.5 3.462,29.5 3.462,26.275
  region net N16809528: 3.458,7.725 3.458,5.542 4.5,4.5 10.538,4.5 10.538,7.725
Signal Layer 3:
  pour cut-out: 88.569,27.02 88.569,25.903 88.112,25.903 88.112,27.02
  pour cut-out: 91.268,48.674 92.386,48.674 92.386,48.216 91.268,48.216
  pour cut-out: 75.283,46.435 76.4,46.435 76.4,45.978 75.283,45.978
  pour cut-out: 91.883,45.399 90.144,43.659 89.586,44.526 91.516,45.999
  pour cut-out: 107.29,42.901 107.29,40.208 106.832,40.208 106.832,42.901
  pour cut-out: 76.124,51.841 76.124,50.724 75.667,50.724 75.667,51.841
  pour cut-out: 72.238,54.788 72.238,53.67 71.78,53.67 71.78,54.788
  pour cut-out: 46.05,44.323 44.933,44.323 44.933,44.78 46.05,44.78
  pour cut-out: 50.004,41.854 51.121,41.854 51.121,41.396 50.004,41.396
  pour cut-out: 53.188,43.866 54.305,43.866 54.305,43.409 53.188,43.409
  pour cut-out: 9.013,53.256 10.131,53.256 10.131,52.799 9.013,52.799
  pour cut-out: 60.985,30.124 60.985,29.007 60.528,29.007 60.528,30.124
  pour cut-out: 58.649,25.756 58.649,24.638 58.191,24.638 58.191,25.756
  pour cut-out: 54.686,34.519 54.686,33.401 54.229,33.401 54.229,34.519
  pour cut-out: 56.744,34.112 56.744,32.995 56.286,32.995 56.286,34.112
  pour cut-out: 58.275,35.636 57.157,35.636 57.157,36.093 58.275,36.093
  pour cut-out: 57.252,40.564 57.252,39.446 56.794,39.446 56.794,40.564
  pour cut-out: 87.02,25.705 85.903,25.705 85.903,26.162 87.02,26.162
  pour cut-out: 81.788,39.395 81.788,37.719 81.331,37.719 81.331,39.395
  pour cut-out: 39.205,25.46 39.205,24.342 37.109,24.342 37.109,25.46
  pour cut-out: 67.929,46.825 66.811,46.825 66.811,47.282 67.929,47.282
  pour cut-out: 62.253,28.041 61.135,28.041 61.135,28.498 62.253,28.498
  pour cut-out: 71.857,19.355 71.857,18.44 69.85,18.44 69.85,19.355
  pour cut-out: 109.957,46.241 109.957,44.691 109.499,44.691 109.499,46.241
  pour cut-out: 108.102,54.305 108.102,53.188 105.74,53.188 105.74,54.305
  pour cut-out: 12.7,51.308 11.582,51.308 11.582,51.765 12.7,51.765
  pour cut-out: 89.393,30.339 90.127,30.673 91.616,30.339 87.629,26.042
  pour cut-out: 102.184,39.04 102.184,37.922 101.727,37.922 101.727,39.04
  pour cut-out: 97.141,43.341 95.401,41.601 94.844,42.469 96.774,43.942
  pour cut-out: 89.477,47.82 89.23,48.438 89.002,48.768 90.239,49.699
  pour cut-out: 78.257,36.093 78.257,34.976 77.8,34.976 77.8,36.093
  pour cut-out: 79.324,29.769 78.207,29.769 78.207,30.226 79.324,30.226
  pour cut-out: 76.175,31.928 73.939,31.928 73.939,32.385 76.175,32.385
  pour cut-out: 74.778,45.491 72.974,45.491 72.974,45.949 74.778,45.949
  pour cut-out: 55.829,54.331 55.829,54.966 59.115,55.992 60.296,54.331
  pour cut-out: 62.834,53.679 61.716,53.679 61.716,54.136 62.834,54.136
  pour cut-out: 59.563,57.226 60.681,57.226 60.681,56.769 59.563,56.769
  pour cut-out: 60.452,32.36 59.334,32.36 59.334,32.817 60.452,32.817
  pour cut-out: 57.937,33.985 56.566,33.985 56.566,34.442 57.937,34.442
  pour cut-out: 62.535,17.018 64.237,17.018 64.237,16.561 62.535,16.561
  pour cut-out: 61.29,17.78 61.29,16.662 61.29,15.799 60.833,17.78
  pour cut-out: 58.369,18.669 56.871,18.669 56.871,19.126 58.369,19.126
  pour cut-out: 45.974,23.139 44.856,23.139 44.856,23.597 45.974,23.597
  pour cut-out: 43.434,31.369 42.723,32.741 43.18,32.741 43.434,31.725
  pour cut-out: 44.78,28.524 44.044,30.48 44.501,30.48 44.501,29.362
  pour cut-out: 47.015,30.963 47.015,32.08 47.473,32.08 47.473,30.963
  pour cut-out: 47.295,32.115 47.295,33.232 50.735,33.232 50.735,32.115
  pour cut-out: 43.561,49.555 43.561,50.673 44.018,50.673 44.018,49.555
Signal Layer 4:
  pour cut-out: 34.982,23.293 34.982,24.817 34.347,24.817 34.347,23.293
  pour cut-out: 53.652,53.723 53.652,55.97 53.017,55.97 53.017,53.723
  pour cut-out: 35.842,49.396 38.088,49.396 38.088,50.031 35.842,50.031
  pour cut-out: 66.322,25.266 68.568,25.266 68.568,27.559 66.322,27.559
  pour cut-out: 99.335,40.08 99.335,38.556 99.97,38.556 99.97,40.08
  pour cut-out: 36.271,25.679 37.579,23.621 37.13,24.509 37.13,26.033
  pour cut-out: 30.656,42.727 29.132,42.727 29.132,42.092 30.656,42.092
  pour cut-out: 33.939,42.877 33.939,44.401 33.304,44.401 33.304,42.877
  pour cut-out: 106.832,25.679 106.832,28.485 106.292,28.485 106.292,25.679
  pour cut-out: 102.152,23.532 102.152,24.751 101.517,24.751 101.517,23.532
  pour cut-out: 100.069,24.37 100.069,25.589 99.434,25.589 99.434,24.37
  pour cut-out: 102.362,47.048 104.761,47.048 104.761,47.683 102.362,47.683
  pour cut-out: 90.939,34.812 90.939,32.182 91.574,32.182 91.574,34.812
  pour cut-out: 42.679,40.933 42.679,39.714 43.314,39.714 43.314,40.933
  pour cut-out: 47.988,54.395 47.988,53.176 48.623,53.176 48.623,54.395
  pour cut-out: 50.248,54.827 50.248,53.608 50.883,53.608 50.883,54.827
  pour cut-out: 73,33.948 73,32.729 74.023,32.729 74.023,33.948
  pour cut-out: 76.336,40.028 76.336,38.809 76.971,38.809 76.971,40.028
  pour cut-out: 62.263,38.901 62.263,37.682 62.898,37.682 62.898,38.901
  pour cut-out: 58.858,35.904 58.858,34.685 59.665,34.685 59.665,35.904
  pour cut-out: 29.09,31.307 29.09,30.087 29.725,30.087 29.725,31.307
  pour cut-out: 48.489,7.544 48.489,6.325 49.124,6.325 49.124,7.544
  pour cut-out: 92.611,33.775 94.857,33.775 94.857,34.41 92.611,34.41
  pour cut-out: 94.582,35.507 94.582,33.26 95.217,33.26 95.217,35.507
  pour cut-out: 104.539,40.612 104.539,38.366 105.174,38.366 105.174,40.612
  pour cut-out: 78.021,32.078 78.021,29.831 78.656,29.831 78.656,32.078
  pour cut-out: 60.14,28.242 60.14,25.996 60.775,25.996 60.775,28.242
  pour cut-out: 24.173,51.706 24.173,49.46 24.808,49.46 24.808,51.706
  pour cut-out: 82.118,43.155 81.727,46.663 80.559,46.663 80.559,43.612
  pour cut-out: 45.449,26.707 45.449,28.231 44.814,28.231 44.814,26.707
  pour cut-out: 87.08,38.696 87.08,40.22 86.445,40.22 86.445,38.696
  pour cut-out: 89.67,36.511 89.67,38.035 89.035,38.035 89.035,36.511
  pour cut-out: 86.034,26.666 86.034,28.19 85.399,28.19 85.399,26.666
  pour cut-out: 79.739,25.538 79.739,27.062 79.104,27.062 79.104,25.538
  pour cut-out: 45.754,35.535 45.754,38.061 45.119,38.061 45.119,35.535
  pour cut-out: 24.46,38.913 24.359,40.27 22.962,39.573 23.749,38.786
  pour cut-out: 29.451,33.564 29.451,35.088 28.816,35.088 28.816,33.564
  pour cut-out: 28.583,32.6 28.583,34.124 27.948,34.124 27.059,32.6
  pour cut-out: 41.097,9.638 41.097,10.922 39.759,10.922 39.759,9.638
  pour cut-out: 78.562,29.108 78.562,30.632 77.394,30.632 77.394,29.108
  pour cut-out: 55.443,33.833 55.443,35.357 54.275,35.357 54.275,33.833
  pour cut-out: 7.01,54.204 7.01,52.68 8.153,52.68 8.153,54.204
  pour cut-out: 36.076,29.577 36.076,31.101 35.441,31.101 35.65,29.577
  pour cut-out: 30.476,28.524 30.476,29.605 28.448,29.605 28.448,28.524
  pour cut-out: 53.887,24.291 52.363,24.291 52.363,23.656 53.887,23.656
  pour cut-out: 74.295,17.052 71.196,17.052 71.196,16.417 74.295,16.417
  pour cut-out: 47.202,17.715 47.202,19.239 45.491,19.812 46.567,17.715
  pour cut-out: 41.842,23.913 41.842,25.437 41.207,25.437 41.207,23.913
  pour cut-out: 51.037,38.498 51.037,40.373 49.869,40.373 49.869,38.498
  pour cut-out: 53.857,45.94 53.857,47.815 52.688,47.815 52.688,45.94
  pour cut-out: 57.912,48.489 57.912,50.013 56.744,50.013 56.744,48.489
  pour cut-out: 57.658,45.923 57.658,47.447 56.49,47.447 56.49,45.923
  pour cut-out: 59.436,44.907 59.436,46.431 58.268,46.431 58.268,44.907
  pour cut-out: 59.995,43.104 59.995,44.628 58.826,44.628 58.826,43.104
  pour cut-out: 60.808,41.605 60.808,43.129 59.639,43.129 59.639,41.605
  pour cut-out: 69.748,40.005 69.748,41.529 68.58,41.529 68.58,40.005
  pour cut-out: 67.234,31.496 67.234,33.02 66.065,33.02 66.065,31.496
  pour cut-out: 60.985,28.6 60.985,30.582 59.817,30.582 59.817,28.6
  pour cut-out: 72.715,27.559 72.715,29.083 70.891,29.083 70.891,27.559
  pour cut-out: 77.318,37.567 77.318,39.091 76.149,39.091 76.149,37.567
  pour cut-out: 92.278,41.605 92.278,43.129 91.11,43.129 91.11,41.605
  pour cut-out: 88.748,40.132 88.748,41.656 87.986,41.656 87.986,40.132
  pour cut-out: 91.161,26.518 91.161,28.042 89.992,28.042 89.992,26.518
  pour cut-out: 102.083,21.59 102.083,23.52 101.244,22.936 100.914,22.352
  pour cut-out: 103.048,36.474 103.048,37.998 101.879,37.998 101.879,36.474
  pour cut-out: 97.359,40.585 97.359,42.109 96.19,42.109 96.19,40.585
  pour cut-out: 65.811,47.981 65.811,45.974 66.98,45.974 66.98,47.981
  pour cut-out: 82.245,53.01 82.245,50.317 83.414,50.317 83.414,53.01
  pour cut-out: 97.468,51.791 96.749,50.267 98.273,50.267 98.273,51.791
  pour cut-out: 63.779,56.642 63.779,55.118 64.948,55.118 64.948,56.642
  pour cut-out: 62.103,57.277 62.103,55.753 63.271,55.753 63.271,57.277
  pour cut-out: 59.639,57.379 59.639,55.855 60.808,55.855 60.808,57.379
  pour cut-out: 56.998,57.353 56.998,55.829 58.166,55.829 58.166,57.353
  pour cut-out: 41.885,57.226 41.885,55.702 43.053,55.702 43.053,57.226
  pour cut-out: 34.629,41.413 34.629,42.937 33.994,42.937 33.994,41.413
  pour cut-out: 37.338,48.407 44.247,48.407 44.247,50.216 37.338,50.216
  pour cut-out: 39.853,52.299 39.853,50.775 40.488,50.775 40.488,52.299
Bottom Layer:
  pour cut-out: 89.967,35.966 92.035,33.696 91.612,33.273 90.519,34.834
  pour cut-out: 45.415,37.299 42.799,37.49 42.85,37.897 45.415,37.767
  pour cut-out: 42.761,39.637 42.875,41.199 43.282,41.148 43.205,39.637
  pour cut-out: 57.286,32.828 57.286,31.648 56.82,31.648 56.744,32.828
  pour cut-out: 76.742,47.69 76.742,46.511 76.276,46.511 75.512,47.275
  pour cut-out: 79.614,36.364 78.435,36.364 78.435,36.83 79.614,36.906
  pour cut-out: 59.675,42.917 58.496,42.917 58.662,43.93 59.675,43.459
  pour cut-out: 61.999,49.274 60.82,49.274 60.82,49.74 61.999,49.816
  pour cut-out: 64.019,49.343 62.84,49.343 62.84,49.809 64.019,49.886
  pour cut-out: 88.338,28.234 85.615,26.336 85.192,26.759 88.03,28.746
  pour cut-out: 88.176,26.504 86.733,25.498 86.018,25.752 87.403,26.397
  pour cut-out: 87.442,27.571 88.734,25.717 87.932,24.915 86.477,26.992
  pour cut-out: 70.508,41.863 71.987,41.986 71.987,41.698 70.508,40.662
  pour cut-out: 68.502,44.812 68.502,42.795 68.08,42.373 67.044,43.852
  pour cut-out: 58.369,30.886 56.236,30.455 55.855,31.039 57.328,31.709
  pour cut-out: 51.877,26.238 50.928,27.6 51.349,28.022 52.385,26.543
  pour cut-out: 41.96,27.32 43.323,28.27 43.744,27.848 42.265,26.812
  pour cut-out: 39.744,33.427 40.341,32.571 39.919,32.149 39.238,33.123
  pour cut-out: 43.993,34.503 42.631,33.554 42.209,33.976 43.688,35.011
  pour cut-out: 45.263,35.103 45.263,36.617 45.685,37.039 46.721,35.56
  pour cut-out: 47.027,38.025 46.525,38.754 47.238,38.754 47.93,38.754
  pour cut-out: 49.782,46.866 50.691,47.5 51.113,47.078 50.086,46.359
  pour cut-out: 44.526,49.885 45.983,49.885 46.005,49.463 44.831,49.022
  pour cut-out: 56.634,48.955 57.996,49.904 64.287,48.447 56.939,48.447
  pour cut-out: 59.846,53.954 59.846,51.079 58.84,52.736
  pour cut-out: 55.991,55.498 54.548,54.492 54.125,54.915 55.685,56.008
  pour cut-out: 58.584,56.824 57.14,55.818 56.73,57.334 58.278,57.334
  pour cut-out: 74.748,52.03 75.754,50.587 75.331,50.164 74.238,51.725
  pour cut-out: 9.21,53.144 9.747,52.374 9.652,52.045 8.534,52.045
  pour cut-out: 90.115,30.15 90.115,31.33 90.538,31.753 91.16,30.865
  pour cut-out: 92.799,33.49 93.919,31.801 93.383,31.624 92.29,33.185
  pour cut-out: 82.347,52.095 81.81,52.866 82.233,53.288 82.855,52.4
  pour cut-out: 79.781,52.705 81.069,53.602 81.491,53.18 80.086,52.197
  pour cut-out: 63.043,43.078 62.818,41.343 62.395,40.92 61.773,41.808
  pour cut-out: 45.898,23.165 44.856,23.165 45.644,23.952
  pour cut-out: 47.715,29.225 46.044,28.505 45.622,28.928 46.649,29.648
  pour cut-out: 44.738,28.946 43.964,30.056 44.387,30.479 45.247,29.251
  pour cut-out: 53.163,29.336 53.933,29.873 54.356,29.45 53.468,28.828
  pour cut-out: 54.686,37.846 55.635,36.484 55.214,36.062 54.178,37.541
  pour cut-out: 53.848,33.934 53.365,34.773 54.508,35.103 54.744,34.472
  pour cut-out: 51.892,34.087 51.355,34.857 51.892,35.74 52.4,34.392
  pour cut-out: 43.533,34.89 44.98,35.258 44.726,35.004 43.838,34.382
  pour cut-out: 46.66,37.973 49.911,39.981 49.911,37.112 49.581,36.881
  pour cut-out: 43.307,43.536 44.077,44.072 44.5,43.649 43.612,43.028
Multi-Layer:
  pour cut-out: 114.7,46.2 108.15,46.2 108.15,54.25 114.7,54.25

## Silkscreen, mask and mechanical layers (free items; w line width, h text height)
Top Overlay:
  lines w0.2: 85.201,56 86.651,56 ; 87.851,56 89.301,56
  text "5V" at 30.322,58.1 h1.2
  text "GND" at 32.3,58.1 h1.2
  text "D12" at 35.1,58.1 h1.2
  text "D11" at 37.7,58.1 h1.2
  text "D10" at 40.2,58.1 h1.2
  text "D9" at 43.1,58.1 h1.2
  text "D8" at 45.6,58.1 h1.2
  text "D7" at 48.2,58.1 h1.2
  text "D6" at 50.639,58.1 h1.2
  text "A12" at 53,58.1 h1.2
  text "A3" at 55.719,58.1 h1.2
  text "A2" at 58.263,58.1 h1.2
  text "A1" at 60.873,58.1 h1.2
  text "NC" at 63.259,58.1 h1.2
  text "GND" at 65.378,58.1 h1.2
  text "3V3" at 68.145,58.1 h1.2
  text "1" at 85.5,57.4 h1.5
  text "1" at 103,57.4 h1.5
  text "2" at 85.5,53.5 h1.5
  text "2" at 103,53.5 h1.5
  text "DEBUG" at 77.5,49.1 h1.6
  text "SIMPLICITY" at 92.075,49.1 h1.6
  text "Si7021" at 108.873,44.521 h2
  text "EXP" at 102.947,43.9 h2
  text "20" at 103.947,42.3 h1.5
  text "19" at 107.847,42.3 h1.5
  text "RESET" at 96.109,33.421 h2
  text "EFM32PG28" at 80.822,23.4 h2
  text "2" at 104.47,16.7 h1.5
  text "1" at 108.763,16.7 h1.5
  text "ADC Input / 0 V - VMCU" at 99.5,12.217 h1.4
  text "BTN1" at 38.45,9.6 h2
  text "BTN0" at 50.325,9.6 h2
  text "LED1" at 60.395,9.6 h2
  text "LED0" at 65.474,9.6 h2
  text "BAT" at 16.7,9 h2
  text "AEM" at 21.2,9 h2
  text "LC Sense" at 81.778,4.7 h2
  text "VMCU" at 28.62,1 h1.2
  text "GND" at 32.358,1 h1.2
  text "D15" at 35.396,1 h1.2
  text "D14" at 37.936,1 h1.2
  text "D13" at 40.519,1 h1.2
  text "C11" at 43.056,1 h1.2
  text "C10" at 45.601,1 h1.2
  text "NC" at 48.3,1 h1.2
  text "B6" at 50.683,1 h1.2
  text "B1" at 53.293,1 h1.2
  text "NC" at 55.8,1 h1.2
  text "NC" at 58.179,1 h1.2
  text "RST" at 60.413,1 h1.2
  text "AIN1" at 62.84,1 h1.2
  text "GND" at 65.978,1 h1.2
  text "3V3" at 68.745,1 h1.2
Bottom Overlay:
  text "PCBB2506A Rev A03" at 1.32,34.29 h1 r90
  text "ADC_VREFP" at 97.501,31.527 h1.7
  text "ADC_VREFN" at 97.501,28.527 h1.7
  text "SPI_CS" at 112.72,28.189 h1.7
  text "SPI_SCK" at 113.827,25.615 h1.7
  text "SPI_MISO" at 114.484,23.23 h1.7
  text "SPI_MOSI" at 114.475,20.975 h1.7
  text "BOARD INFO" at 19.8,15.775 h1.52
  text "BAT" at 7.4,4.1 h1.52
  text "GND" at 7.45,1.45 h1.52
Top Solder:
  the board outline again, w0.8
Bottom Solder:
  the board outline again, w0.8
Board Outline:
  lines w0.1: 109.5,51.5 cw(c109.1,51.5) 109.1,51.1 cw(c109.1,51.5) 108.7,51.5 108.7,53.5 cw(c109.1,53.5) 109.1,53.9 113.8,53.9 cw(c113.8,53.5) 114.2,53.5 114.2,51.5 cw(c113.8,51.5) 113.8,51.1 cw(c113.8,51.5) 113.4,51.5 113.4,53.1 109.5,53.1 109.5,51.5 ; 0,1.2 ccw(c1.2,1.2) 1.2,0 ; 0,1.2 ccw(c1.2,1.2) 1.2,0 ; 0,1.2 0,58.8 ; 0,1.2 0,58.8 ; 0,58.8 cw(c1.2,58.8) 1.2,60 ; 0,58.8 cw(c1.2,58.8) 1.2,60 ; 1.2,0 113.8,0 ; 1.2,0 113.8,0 ; 1.2,60 113.8,60 ; 1.2,60 113.8,60 ; 113.8,0 ccw(c113.8,1.2) 115,1.2 ; 113.8,0 ccw(c113.8,1.2) 115,1.2 ; 113.8,60 cw(c113.8,58.8) 115,58.8 ; 113.8,60 cw(c113.8,58.8) 115,58.8 ; 115,1.2 115,58.8 ; 115,1.2 115,58.8 ; 108.7,46.9 ccw(c109.1,46.9) 109.1,46.5 113.8,46.5 ccw(c113.8,46.9) 114.2,46.9 114.2,48.9 ccw(c113.8,48.9) 113.8,49.3 ccw(c113.8,48.9) 113.4,48.9 113.4,47.3 109.5,47.3 109.5,48.9 ccw(c109.1,48.9) 109.1,49.3 ccw(c109.1,48.9) 108.7,48.9 108.7,46.9
  text "To Be milled out" at 99.4,44.8 h1
Route Tool Path:
  lines w0.1: -0.25,0 0.25,0 ; 0,-0.25 0,0.25 ; 1.175,60 8.5,60 ; 1.2,60 ccw(c1.2,58.8) 0,58.8 0,1.2 ccw(c1.2,1.2) 1.2,0 8.525,0 ; 15.5,0 56.5,0 ; 15.5,60 56.5,60 ; 63.5,0 94.5,0 ; 63.5,60 94.5,60 ; 101.5,0 113.8,0 ccw(c113.8,1.2) 115,1.2 115,58.8 ccw(c113.8,58.8) 113.8,60 101.5,60 ; -2.4,1.2 ccw(c1.2,1.2) 1.2,-2.4 ; -2.4,1.2 ccw(c1.2,1.2) 1.2,-2.4 ; -2.4,1.2 -2.4,58.8 ; -2.4,1.2 -2.4,58.8 ; -2.4,58.8 cw(c1.2,58.8) 1.2,62.4 ; 1.2,-2.4 8.5,-2.4 1.2,-2.4 ; 1.2,62.4 8.5,62.4 1.2,62.4 ; 113.8,-2.4 ccw(c113.8,1.2) 117.4,1.2 ; 113.8,-2.4 ccw(c113.8,1.2) 117.4,1.2 ; 113.8,-2.4 101.5,-2.4 113.8,-2.4 ; 113.8,62.4 cw(c113.8,58.8) 117.4,58.8 ; 113.8,62.4 cw(c113.8,58.8) 117.4,58.8 ; 113.8,62.4 101.5,62.4 113.8,62.4 ; 117.4,1.2 117.4,58.8 ; 117.4,1.2 117.4,58.8 ; 15.5,-2.4 56.5,-2.4 15.5,-2.4 ; 15.5,62.4 56.5,62.4 15.5,62.4 ; 63.5,-2.4 94.5,-2.4 63.5,-2.4 ; 63.5,62.4 94.5,62.4 63.5,62.4
Top Component Outline:
  circle w0.1: c38.4,23.8 r0.8
  circle w0.1: c40.4,23.8 r0.8
  circle w0.1: c62.4,23.8 r0.8
  circle w0.1: c64.4,23.8 r0.8
  circle w0.1: c64.4,49.2 r0.8
  circle w0.1: c62.4,49.2 r0.8
  circle w0.1: c38.4,49.2 r0.8
  circle w0.1: c40.4,49.2 r0.8
  circle w0.1: c42.4,49.2 r0.8
  circle w0.1: c44.4,49.2 r0.8
  circle w0.1: c48.4,49.2 r0.8
  circle w0.1: c46.4,49.2 r0.8
  circle w0.1: c54.4,49.2 r0.8
  circle w0.1: c56.4,49.2 r0.8
  circle w0.1: c52.4,49.2 r0.8
  circle w0.1: c50.4,49.2 r0.8
  circle w0.1: c60.4,49.2 r0.8
  circle w0.1: c58.4,49.2 r0.8
  circle w0.1: c58.4,23.8 r0.8
  circle w0.1: c60.4,23.8 r0.8
  circle w0.1: c50.4,23.8 r0.8
  circle w0.1: c52.4,23.8 r0.8
  circle w0.1: c56.4,23.8 r0.8
  circle w0.1: c54.4,23.8 r0.8
  circle w0.1: c46.4,23.8 r0.8
  circle w0.1: c48.4,23.8 r0.8
  circle w0.1: c44.4,23.8 r0.8
  circle w0.1: c42.4,23.8 r0.8
  lines w0.15: 31.9,23.8 70.9,23.8 70.9,49.2 31.9,49.2 31.9,23.8
Top Component Center:
  lines w0.1: 0,1.2 ccw(c1.2,1.2) 1.2,0 113.8,0 ccw(c113.8,1.2) 115,1.2 115,58.8 ccw(c113.8,58.8) 113.8,60 1.2,60 ccw(c1.2,58.8) 0,58.8 0,1.2 ; 108.7,46.9 ccw(c109.1,46.9) 109.1,46.5 113.8,46.5 ccw(c113.8,46.9) 114.2,46.9 114.2,48.9 ccw(c113.8,48.9) 113.8,49.3 ccw(c113.8,48.9) 113.4,48.9 113.4,47.3 109.5,47.3 109.5,48.9 ccw(c109.1,48.9) 109.1,49.3 ccw(c109.1,48.9) 108.7,48.9 108.7,46.9 ; 108.7,51.5 ccw(c109.1,51.5) 109.1,51.1 ccw(c109.1,51.5) 109.5,51.5 109.5,53.1 113.4,53.1 113.4,51.5 ccw(c113.8,51.5) 113.8,51.1 ccw(c113.8,51.5) 114.2,51.5 114.2,53.5 ccw(c113.8,53.5) 113.8,53.9 109.1,53.9 ccw(c109.1,53.5) 108.7,53.5 108.7,51.5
